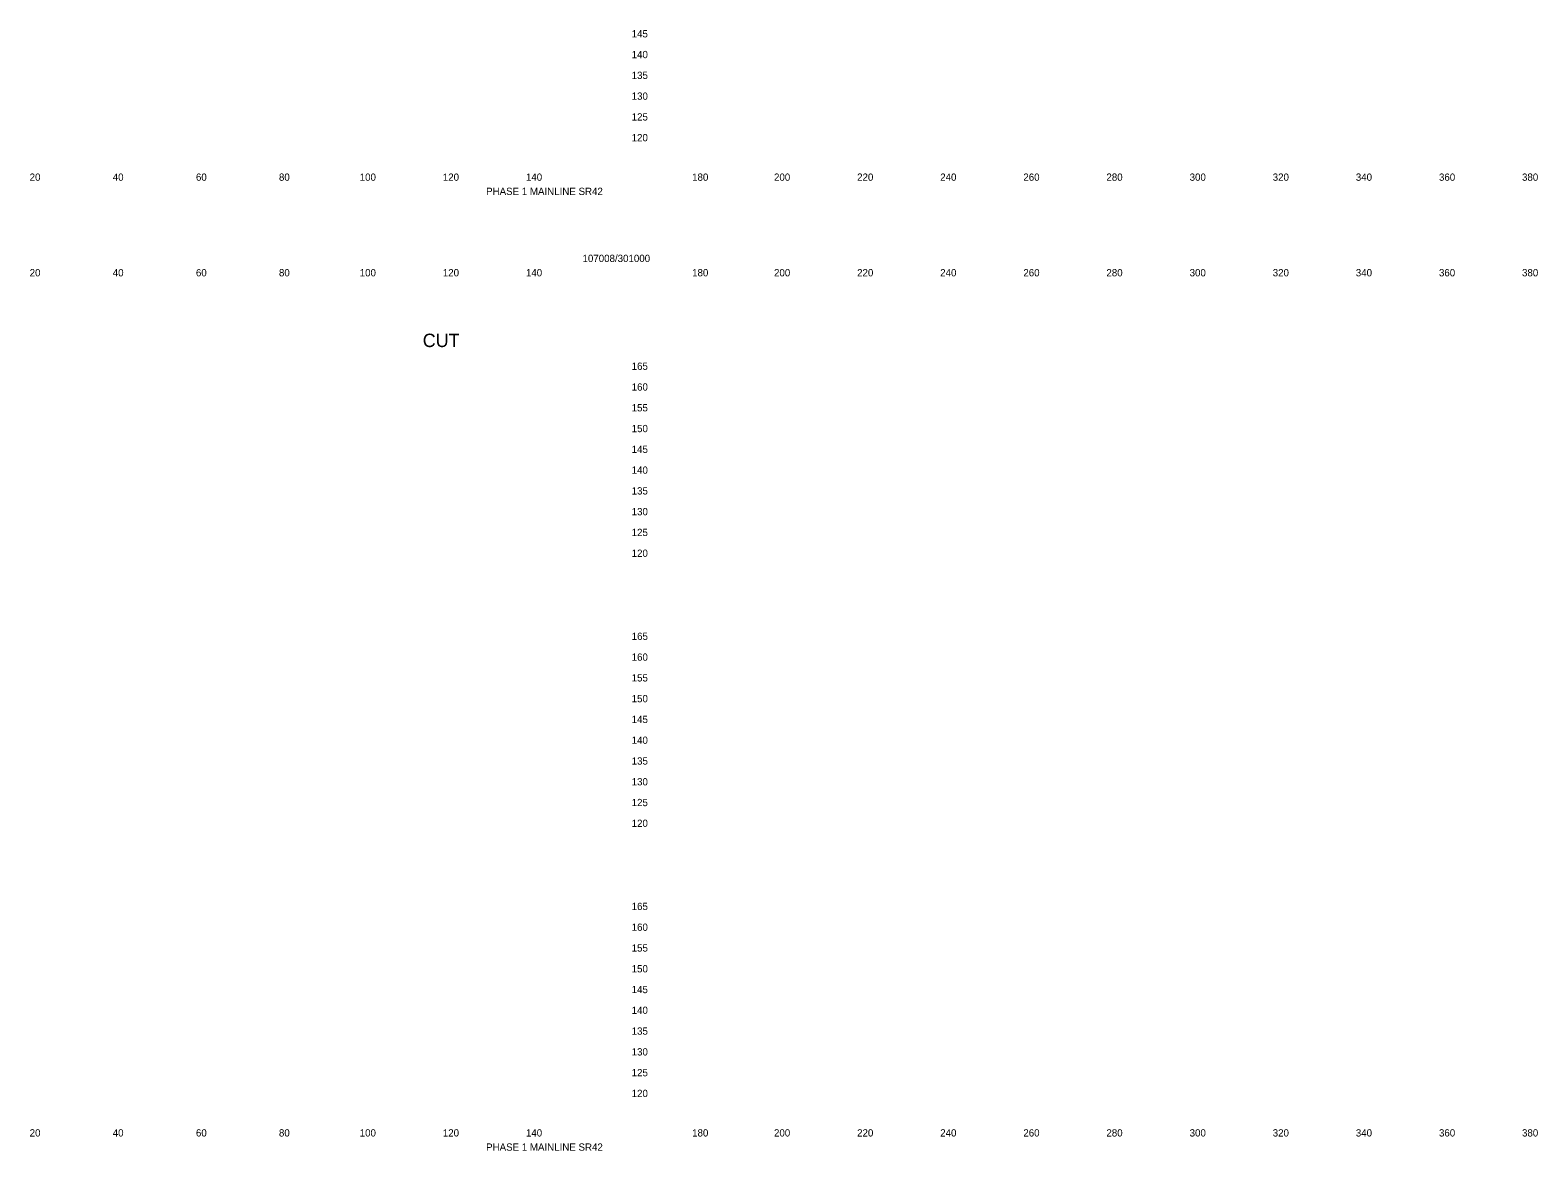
# Model space of a CAD drawing. Extents: x 21281 to 22024, y 6472 to 15198.
# Drawn here: x 21661.4 to 22024.2, y 6471.9 to 6741.6 of the extents above; entities that cross this region are included whole.
import ezdxf

# ---------------------------------------------------------------- set-up
doc = ezdxf.new("R2010")
doc.units = 0
doc.layers.add('XS_SHEET_LABELS_ELEVATION', color=7, linetype='Continuous')
doc.layers.add('XS_SHEET_LABELS_OFFSET', color=7, linetype='Continuous')

msp = doc.modelspace()

# ---------------------------------------------------------------- texts
at = {"layer": 'XS_SHEET_LABELS_ELEVATION'}
for s, p in [('  145  ', (21804.84, 6739.84)), ('  140  ', (21804.84, 6734.84)), ('  135  ', (21804.84, 6729.84)), ('  130  ', (21804.84, 6724.84)), ('  125  ', (21804.84, 6719.84)), ('  120  ', (21804.84, 6714.84)), ('  165  ', (21804.84, 6659.84)), ('  160  ', (21804.84, 6654.84)), ('  155  ', (21804.84, 6649.84)), ('  150  ', (21804.84, 6644.84)), ('  145  ', (21804.84, 6639.84)), ('  140  ', (21804.84, 6634.84)), ('  135  ', (21804.84, 6629.84)), ('  130  ', (21804.84, 6624.84)), ('  125  ', (21804.84, 6619.84)), ('  120  ', (21804.84, 6614.84)), ('  165  ', (21804.84, 6594.84)), ('  160  ', (21804.84, 6589.84)), ('  155  ', (21804.84, 6584.84)), ('  150  ', (21804.84, 6579.84)), ('  145  ', (21804.84, 6574.84)), ('  140  ', (21804.84, 6569.84)), ('  135  ', (21804.84, 6564.84)), ('  130  ', (21804.84, 6559.84)), ('  125  ', (21804.84, 6554.84)), ('  120  ', (21804.84, 6549.84)), ('  165  ', (21804.84, 6529.84)), ('  160  ', (21804.84, 6524.84)), ('  155  ', (21804.84, 6519.84)), ('  150  ', (21804.84, 6514.84)), ('  145  ', (21804.84, 6509.84)), ('  140  ', (21804.84, 6504.84)), ('  135  ', (21804.84, 6499.84)), ('  130  ', (21804.84, 6494.84)), ('  125  ', (21804.84, 6489.84)), ('  120  ', (21804.84, 6484.84))]:
    msp.add_text(s, height=1.75, dxfattribs=at).set_placement(p)
at = {"layer": 'XS_SHEET_LABELS_OFFSET'}
for s, height, p in [('  20  ', 1.75, (21659.95, 6705.34)), ('  40  ', 1.75, (21679.95, 6705.34)), ('  60  ', 1.75, (21699.97, 6705.34)), ('  80  ', 1.75, (21719.95, 6705.34)), ('  100  ', 1.75, (21739.39, 6705.34)), ('  120  ', 1.75, (21759.39, 6705.34)), ('  140  ', 1.75, (21779.39, 6705.34)), ('  180  ', 1.75, (21819.39, 6705.34)), ('  200  ', 1.75, (21839.1, 6705.34)), ('  220  ', 1.75, (21859.1, 6705.34)), ('  240  ', 1.75, (21879.1, 6705.34)), ('  260  ', 1.75, (21899.11, 6705.34)), ('  280  ', 1.75, (21919.1, 6705.34)), ('  300  ', 1.75, (21939.13, 6705.34)), ('  320  ', 1.75, (21959.13, 6705.34)), ('  340  ', 1.75, (21979.13, 6705.34)), ('  360  ', 1.75, (21999.14, 6705.34)), ('  380  ', 1.75, (22019.13, 6705.34)), ('PHASE 1 MAINLINE SR42', 1.75, (21771.11, 6701.92)), ('  20  ', 1.75, (21659.95, 6682.34)), ('  40  ', 1.75, (21679.95, 6682.34)), ('  60  ', 1.75, (21699.97, 6682.34)), ('  80  ', 1.75, (21719.95, 6682.34)), ('  100  ', 1.75, (21739.39, 6682.34)), ('  120  ', 1.75, (21759.39, 6682.34)), ('  140  ', 1.75, (21779.39, 6682.34)), ('107008/301000', 1.75, (21794.31, 6685.79)), ('  180  ', 1.75, (21819.39, 6682.34)), ('  200  ', 1.75, (21839.1, 6682.34)), ('  220  ', 1.75, (21859.1, 6682.34)), ('  240  ', 1.75, (21879.1, 6682.34)), ('  260  ', 1.75, (21899.11, 6682.34)), ('  280  ', 1.75, (21919.1, 6682.34)), ('  300  ', 1.75, (21939.13, 6682.34)), ('  320  ', 1.75, (21959.13, 6682.34)), ('  340  ', 1.75, (21979.13, 6682.34)), ('  360  ', 1.75, (21999.14, 6682.34)), ('  380  ', 1.75, (22019.13, 6682.34)), ('CUT', 3.222, (21755.86, 6665.32)), ('  20  ', 1.75, (21659.95, 6475.34)), ('  40  ', 1.75, (21679.95, 6475.34)), ('  60  ', 1.75, (21699.97, 6475.34)), ('  80  ', 1.75, (21719.95, 6475.34)), ('  100  ', 1.75, (21739.39, 6475.34)), ('  120  ', 1.75, (21759.39, 6475.34)), ('PHASE 1 MAINLINE SR42', 1.75, (21771.11, 6471.92)), ('  140  ', 1.75, (21779.39, 6475.34)), ('  180  ', 1.75, (21819.39, 6475.34)), ('  200  ', 1.75, (21839.1, 6475.34)), ('  220  ', 1.75, (21859.1, 6475.34)), ('  240  ', 1.75, (21879.1, 6475.34)), ('  260  ', 1.75, (21899.11, 6475.34)), ('  280  ', 1.75, (21919.1, 6475.34)), ('  300  ', 1.75, (21939.13, 6475.34)), ('  320  ', 1.75, (21959.13, 6475.34)), ('  340  ', 1.75, (21979.13, 6475.34)), ('  360  ', 1.75, (21999.14, 6475.34)), ('  380  ', 1.75, (22019.13, 6475.34))]:
    msp.add_text(s, height=height, dxfattribs=at).set_placement(p)

doc.saveas('drawing.dxf')
